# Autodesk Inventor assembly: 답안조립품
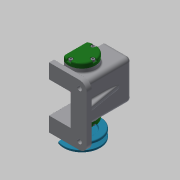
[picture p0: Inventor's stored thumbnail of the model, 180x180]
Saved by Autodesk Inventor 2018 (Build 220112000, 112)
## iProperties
Created: 2022-11
Part Number: 답안조립품
Material: 일반
Document SubType Name: Assembly
Designer: home
Author: home
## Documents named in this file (14)
- C:\Users\kimgi\Desktop\721106V1011\답안조립품.iam
- C:\Users\kimgi\Desktop\721106V1011\본체.ipt
- C:\Users\kimgi\Desktop\721106V1011\앞커버.ipt
- C:\Users\kimgi\Desktop\721106V1011\뒤커버.ipt
- C:\Users\kimgi\Desktop\721106V1011\부시.ipt
- C:\Users\kimgi\Desktop\721106V1011\편심축.ipt
- C:\Users\kimgi\Desktop\721106V1011\베어링 6201.ipt
- C:\Users\kimgi\Desktop\721106V1011\키 4 x 4 x 15.ipt
- C:\Users\kimgi\Desktop\721106V1011\V벨트풀리.ipt
- C:\Users\kimgi\Desktop\721106V1011\링크.ipt
- C:\Users\kimgi\Desktop\721106V1011\슬라이드.ipt
- C:\Users\kimgi\Desktop\721106V1011\핀 5 x 18.ipt
- C:\Users\kimgi\Desktop\721106V1011\볼트 M4 x 12.ipt
- C:\Users\kimgi\Desktop\721106V1011\고정핀 1.2 x 10.ipt
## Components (11 placed, 4 different names)
1. V벨트풀리:1 — 각도:2
2. 핀 5 x 18:1
3. ISO 4762 M4 x 12:1
4. ISO 4762 M4 x 12:2
5. ISO 4762 M4 x 12:3
6. ISO 4762 M4 x 12:4
7. ISO 4762 M4 x 12:5
8. ISO 4762 M4 x 12:6
9. ISO 4762 M4 x 12:7
10. ISO 4762 M4 x 12:8
11. 고정핀 1.2 x 10:1
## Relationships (1: Angle 1)
- 각도:2 [Angle]: V벨트풀리:1
